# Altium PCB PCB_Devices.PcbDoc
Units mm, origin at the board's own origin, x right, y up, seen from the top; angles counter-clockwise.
Board outline 92.7 x 64.28 mm, 2 copper layers (Top Layer, Bottom Layer); 74 components, 82 nets, 258 pads, 41 vias.
Unrouted connection lines stored in the file: 1.
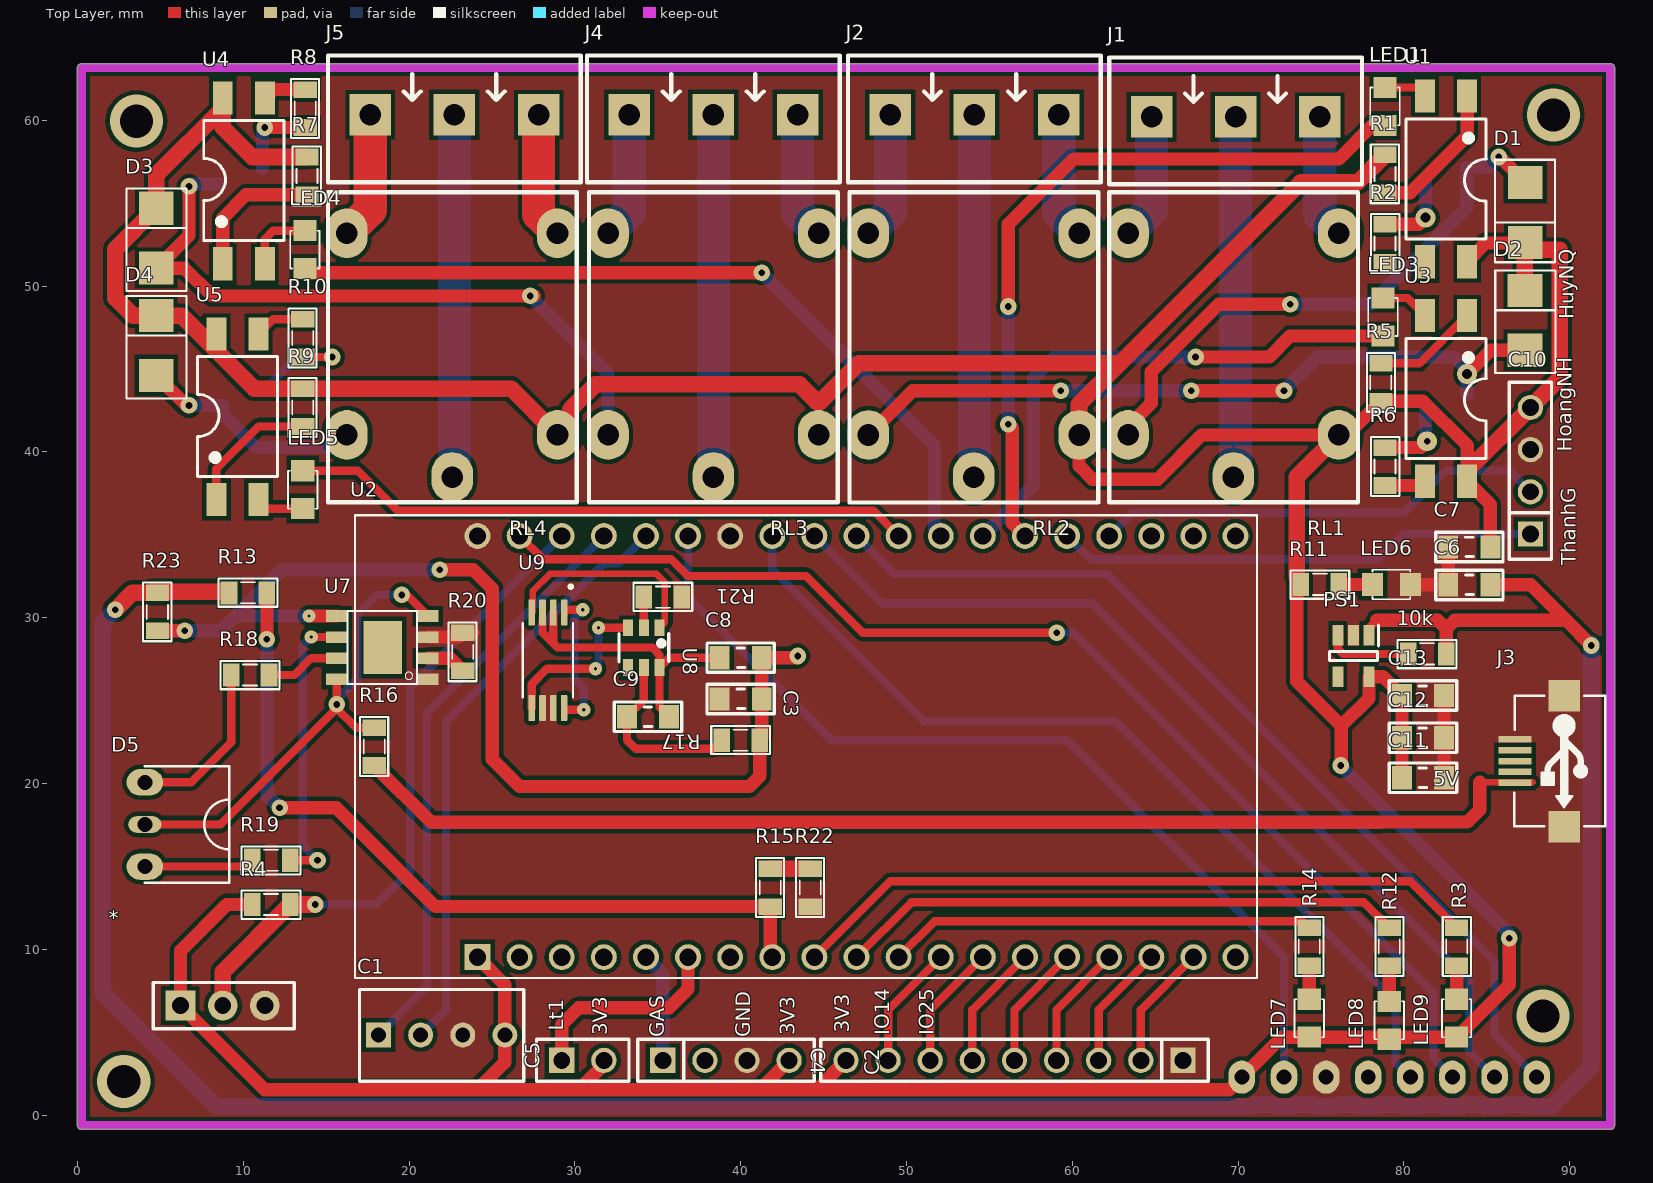
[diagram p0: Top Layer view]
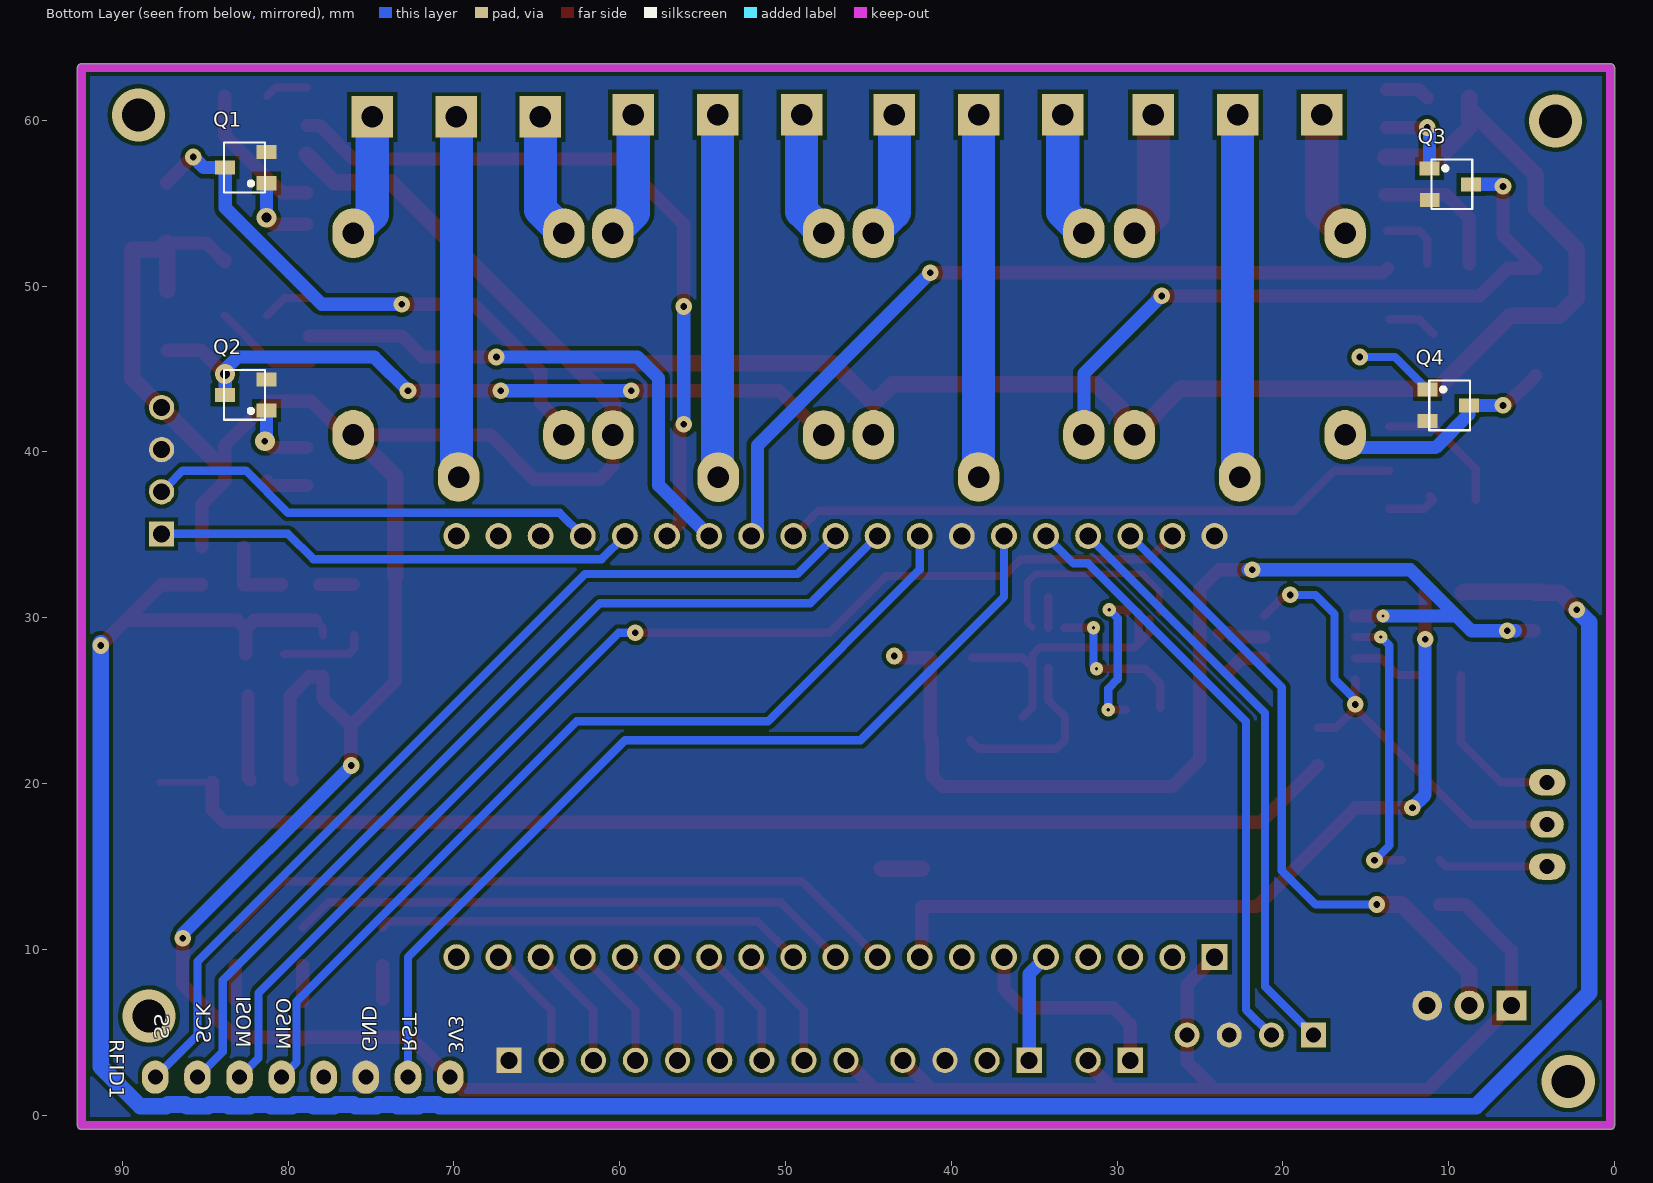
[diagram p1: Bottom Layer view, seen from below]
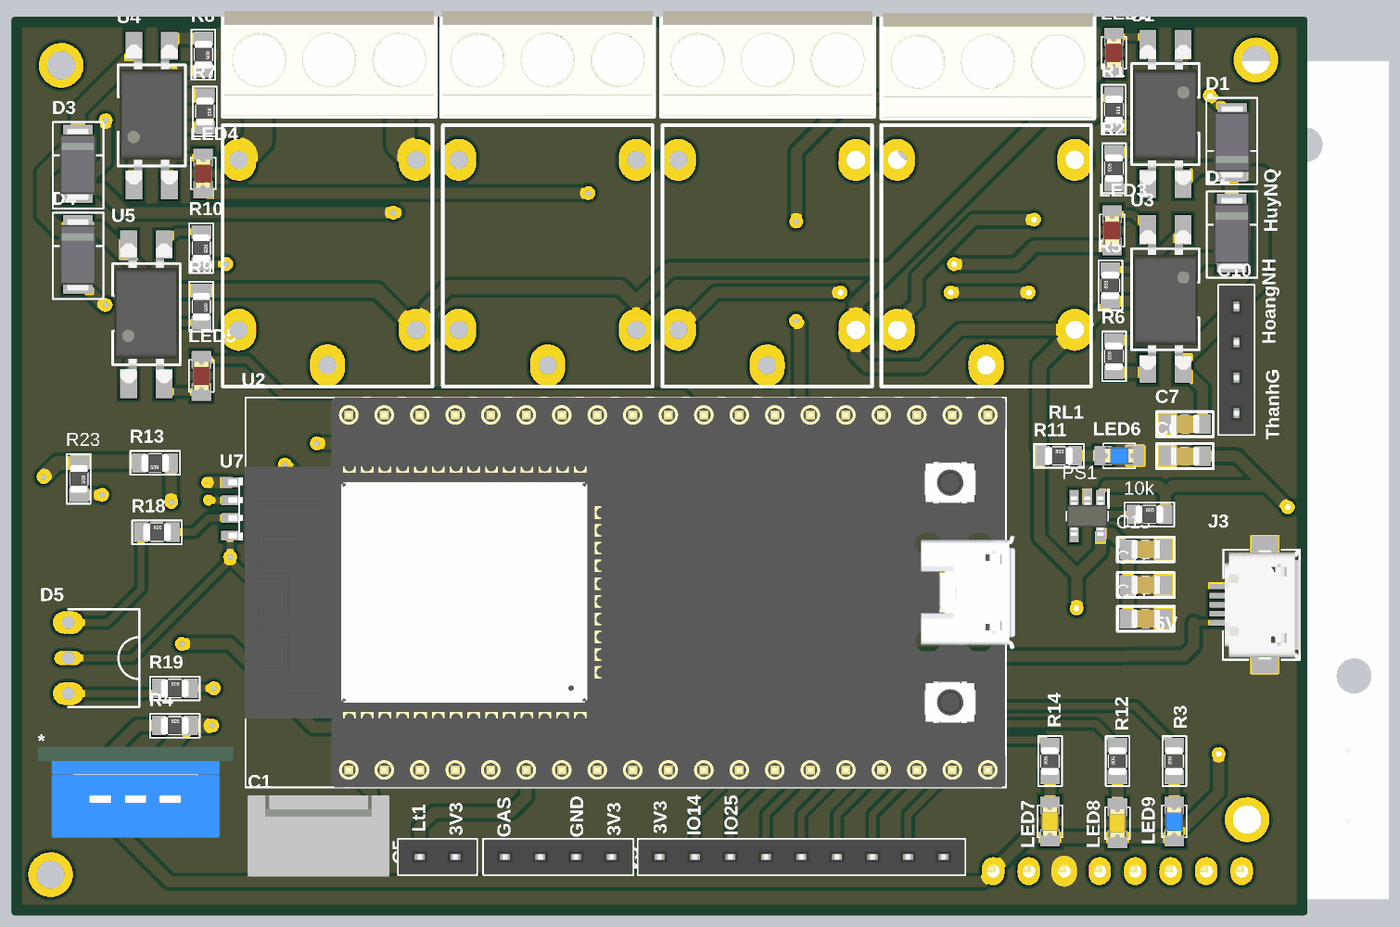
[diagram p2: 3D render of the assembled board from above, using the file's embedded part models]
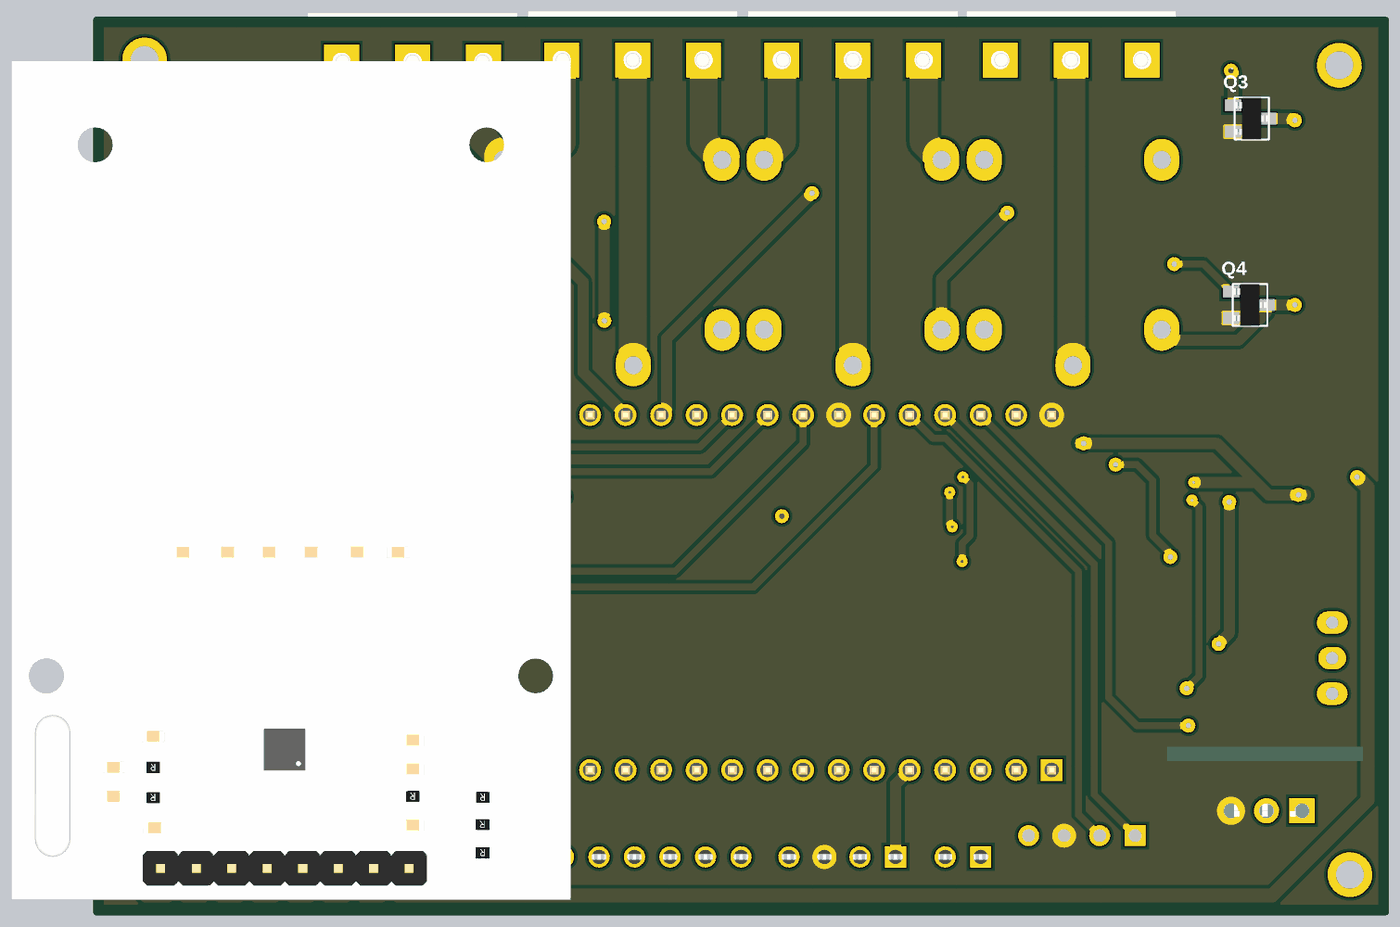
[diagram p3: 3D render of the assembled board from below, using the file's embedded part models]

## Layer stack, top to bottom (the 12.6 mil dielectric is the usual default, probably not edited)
Top Solder: solder mask 0.0102, Solder Resist, Dk 3.5
Top Layer: signal copper 0.0356
Dielectric 1: dielectric 0.32, FR-4, Dk 4.8
Bottom Layer: signal copper 0.0356
Bottom Solder: solder mask 0.0102, Solder Resist, Dk 3.5

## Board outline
0.254,-0.87 cw(c0.254,-0.619) 0.004,-0.619 0.004,63.158 cw(c0.254,63.158) 0.254,63.408 92.456,63.408 cw(c92.456,63.158) 92.706,63.158 92.706,-0.619 cw(c92.456,-0.619) 92.456,-0.87

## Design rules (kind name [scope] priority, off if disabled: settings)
Clearance [All] p1: gap=0.254 ignorepadtopadclearanceinfootprint=FALSE
PolygonConnect [All] p1: connectstyle=Direct reliefconductorwidth=0.254 reliefentries=4 polygonreliefangle="90 Angle" airgapwidth=0.254
RoutingVias [All] p1: holewidth=0.711 width=1.27 viastyle="Through Hole" minholewidth=0.711 minwidth=1.27 maxholewidth=0.711 maxwidth=1.27
SolderMaskExpansion [All] p1: expansion=0.102
Width [All] p1: maxlimit=2 minlimit=0.3 preferedwidth=0.5
30 further rules are at their usual default settings.

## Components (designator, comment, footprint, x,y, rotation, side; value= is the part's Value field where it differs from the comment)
10k "1k" RES-SMD-0805 81.407,27.813 r0 top
* "DHT11_MODULE" DHT11_MODULE 10.033,6.604 r0 top
C1 "Header4" HDR4 18.161,4.826 r0 top
C2 "JP9" JP9-C1T 56.515,3.302 r180 top
C3 "10uF" CAP_0805 40.005,25.127 r0 top value=33p
C4 "MQ5-MOD" JP4-C1T 35.306,3.302 r0 top
C5 "JP2" JP2-C1T 29.21,3.302 r0 top
C6 "1uF" CAP_0805 83.947,32.004 r0 top value=33p
C7 "100nF" CAP_0805 83.947,34.29 r0 top value=33p
C8 "10uF" CAP_0805 40.005,27.613 r0 top value=33p
C9 "100nF" CAP_0805 34.417,24.003 r180 top value=33p
C10 "JP4" JP4-C1T 87.63,35.052 r90 top
C11 "100nF" CAP_0805 81.153,20.32 r180 top value=33p
C12 "100nF" CAP_0805 81.153,22.733 r180 top value=33p
C13 "4.7uf" CAP_0805 81.153,25.273 r180 top value=33p
D1 "M7" DO-214AC(SMA) 87.249,54.991 r90 top
D2 "M7" DO-214AC(SMA) 87.376,47.371 r270 top
D3 "M7" DO-214AC(SMA) 4.826,52.324 r270 top
D4 "M7" DO-214AC(SMA) 4.826,45.847 r270 top
D5 "G/R" "LED_3MM_DUAL RA" 4.064,17.526 r90 top value="B/R LED"
J1 "KF3" KF3-5.08 74.93,60.198 r180 top
J2 "KF3" KF3-5.08 59.182,60.325 r180 top
J3 "0473461001" USB-M1 86.694,21.349 r270 top
J4 "KF3" KF3-5.08 43.434,60.325 r180 top
J5 "KF3" KF3-5.08 27.813,60.325 r180 top
LED1 "LED" LED-0805-Red 78.867,61.976 r270 top value="LED 3 ly Single Colour"
LED3 "LED" LED-0805-Red 78.74,49.276 r270 top value="LED 3 ly Single Colour"
LED4 "LED" LED-0805-Red 13.716,53.34 r270 top value="LED 3 ly Single Colour"
LED5 "LED" LED-0805-Red 13.589,36.576 r90 top value="LED 3 ly Single Colour"
LED6 "LED" LED-0805-Blue 78.105,32.004 r0 top value="LED 3 ly Single Colour"
LED7 "LED" LED-0805-Orange 74.295,4.699 r90 top value="LED 3 ly Single Colour"
LED8 "LED" LED-0805-Orange 79.121,4.572 r90 top value="LED 3 ly Single Colour"
LED9 "LED" LED-0805-Blue 83.185,4.699 r90 top value="LED 3 ly Single Colour"
PS1 "RT9013-33GB" SOT94P279X130-5N 76.962,27.686 r270 top
Q1 "2N222" SOT23D 82.55,57.15 r90 bottom value=C1815
Q2 "2N222" SOT23D 82.55,43.434 r90 bottom value=C1815
Q3 "2N222" SOT23D 9.906,56.134 r270 bottom value=C1815
Q4 "2N222" SOT23D 10.033,42.799 r270 bottom value=C1815
R1 "470" RES-SMD-0805 78.867,56.769 r270 top
R2 "1k" RES-SMD-0805 78.867,52.578 r90 top
R3 "1k" RES-SMD-0805 83.185,10.16 r90 top
R4 "10K" RES-SMD-0805 11.684,12.7 r0 top
R5 "470" RES-SMD-0805 78.613,44.196 r90 top
R6 "1k" RES-SMD-0805 78.867,39.116 r90 top
R7 "470R" RES-SMD-0805 13.843,56.642 r270 top
R8 "1k" RES-SMD-0805 13.741,60.706 r270 top
R9 "470R" RES-SMD-0805 13.589,42.672 r270 top
R10 "1k" RES-SMD-0805 13.589,46.863 r270 top
R11 "470R" RES-SMD-0805 74.93,32.004 r0 top
R12 "1k" RES-SMD-0805 79.121,10.16 r90 top
R13 "10k" RES-SMD-0805 10.287,31.496 r180 top
R14 "1k" RES-SMD-0805 74.295,10.16 r90 top
R15 "1k" RES-SMD-0805 41.783,13.716 r270 top
R16 "0.4R" RES-SMD-0805 17.907,22.225 r270 top
R17 "100R" RES-SMD-0805 40.005,22.606 r180 top
R18 "1k" RES-SMD-0805 10.414,26.543 r0 top
R19 "1k" RES-SMD-0805 11.684,15.367 r0 top
R20 "1.2K" RES-SMD-0805 23.241,27.94 r270 top
R21 "1K" RES-SMD-0805 35.306,31.242 r180 top
R22 "0R" RES-SMD-0805 44.196,13.716 r270 top
R23 "0R" RES-SMD-0805 4.826,30.353 r270 top
RFID1 "RFID" "RFID RC522" 79.121,2.286 r180 bottom
RL1 "Relay 10A/12V" RELAY5PIN-10A 69.723,38.481 r0 top value="Relay SPDT, 10A, 12V"
RL2 "Relay 10A/12V" RELAY5PIN-10A 54.06,38.475 r0 top value="Relay SPDT, 10A, 12V"
RL3 "Relay 10A/12V" RELAY5PIN-10A 38.354,38.481 r0 top value="Relay SPDT, 10A, 12V"
RL4 "Relay 10A/12V" RELAY5PIN-10A 22.606,38.481 r0 top value="Relay SPDT, 10A, 12V"
U1 "OPTO PC817 SMD" OPTO_SMD 83.82,61.468 r270 top value=PC817
U2 "ESP32-DEVKITC-32D" MODULE_ESP32-DEVKITC-32D 43.89,22.225 r90 top
U3 "OPTO PC817 SMD" OPTO_SMD 83.82,48.227 r270 top value=PC817
U4 "OPTO PC817 SMD" OPTO_SMD 8.763,51.341 r90 top value=PC817
U5 "OPTO PC817 SMD" OPTO_SMD 8.382,37.117 r90 top value=PC817
U7 "TP4056" TP4056 18.39,28.194 r180 top
U8 "DW01A" SOT23-6 34.163,28.194 r180 top
U9 "FS8205A" FS8205A 28.321,27.432 r270 top

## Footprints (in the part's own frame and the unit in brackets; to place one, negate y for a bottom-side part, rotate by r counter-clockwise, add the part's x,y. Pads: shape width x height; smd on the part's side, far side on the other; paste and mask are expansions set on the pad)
CAP_0805 [mm]
  rect 1.2x1.4 smd: 1(-1.27,-0.025) 2(1.27,-0.025)
  silkscreen extent -2.03,-0.91 2.03,0.86, body extent -1.01,-0.66 1.01,0.61, height 0.61
DHT11_MODULE [mm]
  rect 1.8x1.8 hole 1.02: 1(-3.81,0)
  round 1.8 hole 1.02: 2(-1.27,0) 3(1.27,0)
  silkscreen extent -5.46,-1.4 3.05,1.4, body extent -8.16,-1.93 5.84,4.57, height 28.5
DO-214AC(SMA) [mm] "DO-214AC Diode Smallest Size"
  rect 2x2.1 smd: 1(1.245,-0.076) 2(-2.367,-0.076)
  silkscreen extent -3.56,-1.86 2.62,1.76, body extent -3.13,-1.38 2.07,1.22, height 2.4
FS8205A [mm]
  rrect25% 1.56x0.4 smd: 1(-2.88,1.031) 2(-2.88,0.381) 3(-2.88,-0.269) 4(-2.88,-0.919) 5(2.88,-0.919) 6(2.88,-0.269) 7(2.88,0.381) 8(2.88,1.031)
  silkscreen extent -4.54,-1.46 2.25,1.57, body extent -3.2,-1.4 3.2,1.53, height 1.2
HDR4 [mm] "Connector; Header; 4 Position"
  rect 1.5x1.5 hole 0.9: 1(0,0)
  round 1.5 hole 0.9: 2(2.54,0) 3(5.08,0) 4(7.62,0)
  silkscreen extent -1.14,-2.79 8.76,2.74, body extent -1.27,-2.92 8.89,2.88, height 11.72
JP2-C1T [mm] "2 row, straight, gold plating"
  rect 1.52x1.52 hole 1.02: 1(0,0)
  round 1.52 hole 1.02: 2(2.54,0)
  silkscreen extent -1.52,-1.27 4.06,1.27, body extent -1.52,-1.25 4.06,1.25, height 8.51
JP4-C1T [mm] "4 row, straight, gold plating"
  rect 1.52x1.52 hole 1.02: 1(0,0)
  round 1.52 hole 1.02: 2(2.54,0) 3(5.08,0) 4(7.62,0)
  silkscreen extent -1.52,-1.27 9.14,1.27, body extent -1.52,-1.25 9.14,1.25, height 8.51
JP9-C1T [mm] "9 row, straight, gold plating"
  rect 1.52x1.52 hole 1.02: 1(-10.16,0)
  round 1.52 hole 1.02: 2(-7.62,0) 3(-5.08,0) 4(-2.54,0) 5(0,0) 6(2.54,0) 7(5.08,0) 8(7.62,0) 9(10.16,0)
  silkscreen extent -11.68,-1.27 11.68,1.27, body extent -11.68,-1.25 11.68,1.25, height 8.51
KF3-5.08 [mm]
  rect 2.5x2.5 hole 1.3: 1(0,0) 2(5.08,0) 3(10.147,0)
  silkscreen extent -2.54,-3.58 12.7,4.06, body extent -2.42,-3.51 12.58,3.99, height 10
LED-0805-Blue [mil]
  rect 50x55 smd: 1(0,0) 2(90,0)
  silkscreen extent 0,-35 90,35, body extent 5,-25 85,25, height 43
LED-0805-Orange [mil]
  rect 50x55 smd: 1(0,0) 2(90,0)
  silkscreen extent 0,-35 90,35, body extent 5,-25 85,25, height 43
LED-0805-Red [mil]
  rect 50x55 smd: 1(0,0) 2(90,0)
  silkscreen extent 0,-35 90,35, body extent 5,-25 85,25, height 43
"LED_3MM_DUAL RA" [mm]
  oval 1.6x2.2 hole 0.9: 1(-2.54,0) 3(2.54,0)
  oval 1x2 / inner oval 1.5x2 / far side oval 1.6x2 hole 0.9: 2(0,0)
  silkscreen extent -3.5,-5.08 3.5,0, body extent -2.84,-2.02 2.84,2.02, height 6.4
MODULE_ESP32-DEVKITC-32D [mm]
  rect 1.56x1.56 hole 1.04: 1(-12.7,19.76)
  round 1.56 hole 1.04: 2(-12.7,17.22) 3(-12.7,14.68) 4(-12.7,12.14) 5(-12.7,9.6) 6(-12.7,7.06) 7(-12.7,4.52) 8(-12.7,1.98) 9(-12.7,-0.56) 10(-12.7,-3.1) 11(-12.7,-5.64) 12(-12.7,-8.18) 13(-12.7,-10.72) 14(-12.7,-13.26) 15(-12.7,-15.8) 16(-12.7,-18.34) 17(-12.7,-20.88) 18(-12.7,-23.42) 19(-12.7,-25.96) 20(12.7,19.76) 21(12.7,17.22) 22(12.7,14.68) 23(12.7,12.14) 24(12.7,9.6) 25(12.7,7.06) 26(12.7,4.52) 27(12.7,1.98) 28(12.7,-0.56) 29(12.7,-3.1) 30(12.7,-5.64) 31(12.7,-8.18) 32(12.7,-10.72) 33(12.7,-13.26) 34(12.7,-15.8) 35(12.7,-18.34) 36(12.7,-20.88) 37(12.7,-23.42) 38(12.7,-25.96)
  silkscreen extent -13.95,-27.25 13.95,27.15, body extent -13.97,-27.9 13.97,27.2, height 8.25
OPTO_SMD [mm]
  rect 2x1.2 smd: 1(0,0) 2(0,-2.54) 3(10,-2.54) 4(10,0)
  silkscreen extent 1.4,-3.68 8.64,1.15, body extent 0.08,-3.56 10.08,1.02, height 3.95
RELAY5PIN-10A [mm]
  oval 2.5x3 hole 1.3: 1(0,0) 2(-6.35,14.7) 3(6.35,14.7) 4(-6.35,2.54) 5(6.35,2.54)
  silkscreen extent -7.49,-1.52 7.51,17.18, body extent -7.49,-1.52 7.49,17.14, height 16
RES-SMD-0805 [mil]
  rect 39.37x55 smd: 1(-45,0) 2(45,0)
  silkscreen extent -70,-34 70,33, body extent -39,-25 39,25, height 31
"RFID RC522" [mm] "RFID RC522"
  oval 1.6x2 hole 0.9: 1(-8.89,0) 2(-6.35,0) 3(-3.81,0) 4(-1.27,0) 5(1.27,0) 6(3.81,0) 7(6.35,0) 8(8.89,0)
  body extent -19.43,-2.03 20.57,57.97, height 15.74
SOT23-6 [mm]
  rect 0.6x1 smd: 1(-0.95,-1.2) 2(0,-1.2) 3(0.95,-1.2) 4(0.95,1.2) 5(0,1.2) 6(-0.95,1.2)
  silkscreen extent -1.5,-0.85 1.5,0.85, body extent -1.46,-1.17 1.46,1.17, height 1
SOT23D [mm] "SOT 23C - 1-3-2 - BCE"
  rect 0.85x1.2 smd: 1(-0.95,-1.25) 2(0.94,-1.245) 3(0,1.25)
  silkscreen extent -1.5,-1.14 1.5,1.32, body extent -1.5,-1.17 1.5,1.33, height 1.06
SOT94P279X130-5N [mm]
  rect 1.25x0.65 smd: 1(-1.25,0.94) 2(-1.25,0) 3(-1.25,-0.94) 4(1.25,-0.94) 5(1.25,0.94)
  silkscreen extent -1.88,-1.45 0.28,1.51, body extent -1.4,-1.45 1.4,1.45, height 1.3
TP4056 [mm]
  rect 1.3x0.7 smd: 1(-2.75,1.905) 2(-2.75,0.635) 3(-2.75,-0.635) 4(-2.75,-1.905) 5(2.75,-1.905) 6(2.75,-0.635) 7(2.75,0.635) 8(2.75,1.905)
  rect 2.3x3.2 smd: GND(-0.025,0)
  silkscreen extent -2.1,-2.2 2.1,2.2, body extent -3.13,-2.45 2.87,2.45, height 1.75
USB-M1 [mm]
  rect 0.4x2 smd: 1(1.3,0) 2(0.65,0) 3(0,0) 4(-0.65,0) 5(-1.321,0)
  rect 1.9x1.9 smd: 5(-3.95,2.968) 5(3.95,2.968)
  silkscreen extent -3.94,-0.03 3.94,5.46, body extent -3.98,0.11 4,5.54, height 2.71

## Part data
10k R1 R2 R3 R4 R5 R6 R7 R8 R9 R10 R11 R12 R13 R14 R15 R16 R17 R18 R19 R20 R21 R22 R23: library part "Resistor - SMD", "Resistor", Manufacturer="Generic Components"
C1: "Header IDC, 4 x 1 Pin Vertical 2.54mm Pitch (Non-Boxed, Male)", Manufacturer="W¨¹rth Elektronik eiSos GmbH", partNo=613002143121
C2: "WR-PHD 2.54 mm Angled Socket Header", Manufacturer="W¨¹rth Elektronik eiSos GmbH", partNo=613009143121
C3 C6 C7 C8 C9 C11 C12 C13: library part CapSMD, "Capacitor"
C4: Manufacturer="W¨¹rth Elektronik eiSos GmbH", partNo=613004143121
C5: "WR-PHD 2.54 mm Angled Socket Header", Manufacturer="W¨¹rth Elektronik eiSos GmbH", partNo=613002143121
C10: "WR-PHD 2.54 mm Angled Socket Header", Manufacturer="W¨¹rth Elektronik eiSos GmbH", partNo=613004143121
D1 D2 D3 D4: library part "Diode M7 ( 4007 )", "Dán"
D5: library part LED_3MM_RA, "LED BLUE/RED DIFFUSED T-1 T/H 3MM", MFR=SunLED, MPN=XLMDKCBD34M
J1 J2 J4 J5: Manufacturer="Würth Elektronik eiSos GmbH", partNo=691103110003
J3: "Connector", Manufacturer_Name=Molex, Mouser Part Number=N/A
LED1 LED3 LED4 LED5 LED6 LED7 LED8 LED9: "LED Single colour Green and Red"
PS1: "Power Supply", Manufacturer_Name=RICHTEK
Q1 Q2 Q3 Q4: "NPN 600mW, ECB"
RFID1: library part "RFID RC522"
RL1 RL2 RL3 RL4: library part "Relay 5", "Relay SPDT,10A - 12VDC 5 Pin"
U1 U3 U4 U5: "Single Opto"
U2: "EVAL BOARD FOR ESP-WROOM-32", Package=None
U7: "Complete single cell Li-Ion battery with a constant current / constant voltage linear charger"
U8: "One Cell Lithium-ion/Polymer Battery Protection IC"

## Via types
v1: diameter 1, hole 0.4, Top Layer to Bottom Layer, 28 vias
v2: diameter 0.8, hole 0.2, Top Layer to Bottom Layer, 6 vias
v3: diameter 3.2, hole 2, Top Layer to Bottom Layer, 4 vias
v4: diameter 1.2, hole 0.6, Top Layer to Bottom Layer, 2 vias
v5: diameter 1.2, hole 0.4, Top Layer to Bottom Layer, 1 vias

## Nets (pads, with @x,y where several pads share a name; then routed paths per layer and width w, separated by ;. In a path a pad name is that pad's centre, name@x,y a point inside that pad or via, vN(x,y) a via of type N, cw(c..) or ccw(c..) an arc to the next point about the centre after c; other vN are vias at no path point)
+3V3: *.1 C1.4 C2.9 C4.4 C5.2 C7.2 C10.4 C11.2 C12.2 C13.2 D1.2 D2.2 D3.2 D4.2 LED7.1 LED8.1 LED9.1 PS1.5 R1.1 R4.1 R5.1 R7.1 R9.1 R11.1 RFID1.8 RL1.5 RL2.5 RL3.5 RL4.5 U1.4 U2.1 U3.4 U4.4 U5.4 | length 337
  Top Layer w0.8: R4.1 9.017,12.7 6.223,9.906 *.1 11.303,1.524 24.13,1.524 ; U2.1 25.781,7.874 C1.4 25.781,3.175 24.13,1.524 ; C5.2 31.75,3.048 30.226,1.524 ; C4.4 41.148,1.524 ; C2.9 44.577,1.524 ; RL2.5 60.41,39.158 61.214,38.354 65.151,38.354 67.818,41.021 RL1.5 76.581,41.021 R5.1 81.153,43.053 83.82,40.386 83.82,38.862 U3.4 85.217,36.83 C7.2 ; R11.1@73.533,32.512 73.533,26.162 76.225,23.47 ; v1(76.2,21.082) 76.225,21.107 76.225,23.47 ; C11.2@79.756,20.218 C11.2 C12.2 C13.2 78.745,26.436 PS1.5 77.902,25.146 76.225,23.47 ; U1.4@83.82,51.593 U1.4 84.95,52.598 D1.2@87.3,52.598 ; v1(86.36,10.668) 86.36,7.874 LED9.1 79.248,4.699 LED8.1 78.994,4.699 LED7.1 72.644,4.699 RFID1.8 69.469,1.524 44.577,1.524 ; 24.13,1.524 30.226,1.524 ; 30.226,1.524 41.148,1.524 ; 41.148,1.524 44.577,1.524
  Top Layer w1: U4.4 U4.4@8.763,60.706 ; R7.1 10.541,57.785 8.763,59.563 U4.4@8.763,60.706 ; RL2.5 60.41,42.884 62.865,45.339 ; R11.1@73.533,32.512 73.533,38.481 RL1.5 ; R1.1 77.216,56.261 73.787,56.261 62.865,45.339 ; U3.4@83.82,38.862 C10.4 89.408,44.45 89.408,52.197 87.752,52.197 D1.2 87.3,52.598 D2.2 ; U4.4@8.763,60.706 4.75,56.693 D3.2 2.286,52.228 2.286,49.276 3.348,48.214 D4.2 6.269,48.214 10.668,43.815 R9.1 26.162,43.815 RL4.5 29.718,41.783 29.718,42.545 31.242,44.069 43.561,44.069 44.704,42.926 47.117,45.339 62.865,45.339
  Bottom Layer w0.8: v1(76.2,21.082) 86.36,10.922 v1(86.36,10.668)
+5V: J3.1 R16.2 | length 73.2
  Top Layer w0.4: 84.582,20.066 87.757,20.066
  Top Layer w0.8: R16.2 21.336,17.653 78.613,17.653 79.991,17.678 83.845,17.678 84.582,18.415 84.582,20.066
GAS_OUT: C4.1 U2.5 | length 6.6
  Bottom Layer w0.8: U2.5 35.306,8.509 C4.1
GND: *.3 C1.3 C2.1 C3.1 C4.3 C6.1 C7.1 C10.3 C11.1 C12.1 C13.1 J3.5 LED6.2 PS1.2 Q1.2 Q2.2 Q3.2 Q4.2 R20.1 R21.1 R22.2 RFID1.6 U2.20 U2.26 U7.1 U7.3 U9.6 U9.7 | length 12.3
  Top Layer w0.5: R20.1@23.749,28.829 24.003,29.083
  Top Layer w0.8: U7.3 22.987,28.829 R20.1 ; LED6.2 80.416,31.979 C6.1 C7.1 ; C11.1@82.296,20.218 C11.1 C12.1 C13.1
Light_2: C5.1 U2.6 | length 12.6
  Top Layer w0.8: C5.1 29.21,5.461 30.226,6.477 35.687,6.477 36.83,7.62 U2.6
LIPO: C3.2 C8.2 R17.1 R23.2 U7.5 | length 65.8
  Top Layer w0.8: R23.2 v1(6.477,29.21) ; v2(13.97,30.099) U7.5 ; v1(21.844,32.893) 23.876,32.893 25.019,31.75 25.019,21.463 26.67,19.812 40.513,19.812 41.148,20.447 R17.1 41.275,22.733 C3.2 C8.2 43.336,27.588 v1(43.434,27.686)
  Bottom Layer w0.8: 5.969,29.21 v1(6.477,29.21) 8.636,29.21 9.525,30.099 ; v2(13.97,30.099) 9.525,30.099 ; v1@22.098,32.893 v1(21.844,32.893) 12.319,32.893 9.525,30.099
Net10k_1: 10k.1 PS1.3 | length 5.2
  Top Layer w0.5: PS1.3 76.022,28.118 76.333,27.807 80.258,27.807 10k.1
NetC1_1: C1.1 U2.23 | length 35.7
  Bottom Layer w0.5: C1.1 21.082,7.747 21.082,24.257 U2.23
NetC2_2: C2.2 U2.18 | length 7.5
  Top Layer w0.5: C2.2 64.135,6.35 U2.18
NetC2_3: C2.3 U2.17 | length 7.5
  Top Layer w0.5: C2.3 61.595,6.35 U2.17
NetC2_4: C2.4 U2.16 | length 7.5
  Top Layer w0.5: C2.4 59.055,6.35 U2.16
NetC2_5: C2.5 U2.15 | length 7.5
  Top Layer w0.5: C2.5 56.515,6.35 U2.15
NetC2_6: C2.6 U2.14 | length 7.5
  Top Layer w0.5: C2.6 53.975,6.35 U2.14
NetC2_7: C2.7 U2.13 | length 7.5
  Top Layer w0.5: C2.7 51.435,6.35 U2.13
NetC2_8: C2.8 U2.12 | length 7.5
  Top Layer w0.5: C2.8 48.895,6.35 U2.12
NetC8_1: C8.1 C9.1 U8.6 U9.2 U9.3 | length 18.1
  Top Layer w0.5: U9.3@28.052,29.902 28.052,29.098 28.702,28.448 ; U9.2 28.702,28.448 ; C9.1 35.113,24.602 U8.6 ; C8.1 35.707,27.588 U8.6 ; 28.702,28.448 28.956,28.194 34.671,28.194 35.113,27.752 U8.6
NetC9_2: C9.2 R17.2 U8.5 | length 10.9
  Top Layer w0.5: U8.5 34.163,25.044 C9.2 33.147,22.606 33.655,22.098 38.354,22.098 R17.2
NetC10_1: C10.1 U2.34 | length 29.5
  Bottom Layer w0.5: U2.34 61.087,33.528 78.486,33.528 80.01,35.052 C10.1 C10.1@88.011,35.052
NetC10_2: C10.2 U2.35 | length 28
  Bottom Layer w0.5: U2.35 63.627,36.322 80.01,36.322 82.55,38.862 86.36,38.862 87.376,37.846 C10.2@88.138,37.846
NetD1_1: D1.1 Q1.3 RL1.4 | length 34.4
  Top Layer w0.8: RL1.4 63.373,41.529 64.77,42.926 64.77,44.831 68.834,48.895 v1(73.152,48.895) ; v1(85.725,57.785) 85.776,57.785 D1.1
  Bottom Layer w0.8: v1(73.152,48.895) 77.978,48.895 83.8,54.717 Q1.3 85.09,57.15 v1(85.725,57.785)
NetD2_1: D2.1 Q2.3 RL2.4 | length 44
  Top Layer w0.8: RL2.4 50.382,43.688 v1(59.309,43.688) ; v1(67.183,43.688) v1(72.771,43.688) ; v4(83.8,44.684) 85.242,46.126 D2.1
  Bottom Layer w0.8: v1(59.309,43.688) v1(67.183,43.688) ; v1(72.771,43.688) 74.803,45.72 83.058,45.72 83.8,44.978 v4(83.8,44.684) Q2.3
NetD3_1: D3.1 Q3.3 RL3.4 | length 41.6
  Top Layer w0.8: v1(6.731,56.007) 6.731,53.061 D3.1 6.452,51.079 8.128,49.403 v1(27.305,49.403) v1@27.559,49.403
  Bottom Layer w0.8: v1(6.731,56.007) 6.858,56.134 Q3.3 ; v1(27.305,49.403) 32.004,44.704 RL3.4
NetD4_1: D4.1 Q4.3 RL4.4 | length 13.9
  Top Layer w0.8: D4.1 6.553,42.799 v1(6.731,42.799)
  Bottom Layer w0.8: v1(6.731,42.799) Q4.3 8.783,42.271 10.795,40.259 15.494,40.259 RL4.4
NetD5_1: D5.1 R19.1 | length 6.6
  Top Layer w0.5: D5.1 10.16,14.986 R19.1
NetD5_2: D5.2 R16.1 U7.4 U7.8 | length 30.6
  Top Layer w0.5: D5.2@3.683,17.526 D5.2 8.636,17.526 v1@15.64,24.53 ; U7.8 v1(15.64,24.765) v1@15.64,24.53 ; R16.1 16.801,23.368 v1@15.64,24.53 ; v1(19.558,31.369) 19.87,31.369 U7.4
  Bottom Layer w0.5: v1(15.64,24.765) 15.64,25.038 16.891,26.289 16.891,30.226 18.034,31.369 v1(19.558,31.369)
NetD5_3: D5.3 R18.1 | length 10.3
  Top Layer w0.5: D5.3 6.858,20.066 9.271,22.479 R18.1
NetJ1_1: J1.1 RL1.3 | length 7.5
  Bottom Layer w2: J1.1 74.93,54.324 RL1.3
NetJ1_2: J1.2 RL1.1 | length 21.8
  Bottom Layer w2: RL1.1 69.85,38.608 J1.2
NetJ1_3: J1.3 RL1.2 | length 7.6
  Bottom Layer w2: RL1.2 64.783,54.591 J1.3
NetJ2_1: J2.1 RL2.3 | length 7.7
  Bottom Layer w2: J2.1 59.182,54.403 RL2.3
NetJ2_2: J2.2 RL2.1 | length 22.1
  Bottom Layer w2: RL2.1 54.102,38.518 J2.2 J2.2@54.102,60.579
NetJ2_3: J2.3 RL2.2 | length 7.7
  Bottom Layer w2: RL2.2 49.035,54.5 J2.3
NetJ4_1: J4.1 RL3.3 | length 7.7
  Bottom Layer w2: J4.1 43.434,54.451 RL3.3
NetJ4_2: J4.2 RL3.1 | length 21.8
  Bottom Layer w2: RL3.1 J4.2
NetJ4_3: J4.3 RL3.2 | length 7.7
  Bottom Layer w2: RL3.2 33.287,54.464 J4.3
NetJ5_1: J5.1 RL4.3 | length 7.6
  Top Layer w2: J5.1 27.813,54.324 RL4.3
NetJ5_2: J5.2 RL4.1 | length 21.9
  Bottom Layer w2: RL4.1 22.733,38.608 J5.2
NetJ5_3: J5.3 RL4.2 | length 7.7
  Top Layer w2: RL4.2 17.666,54.591 J5.3
NetLED1_1: LED1.1 U1.2 | length 2.6
  Top Layer w0.5: LED1.1 80.772,61.976 U1.2
NetLED3_1: LED3.1 U3.2 | length 3
  Top Layer w0.5: LED3.1 80.231,49.276 U3.2
NetLED4_1: LED4.1 U4.2 | length 4.1
  Top Layer w0.5: U4.2 11.303,52.832 11.811,53.34 LED4.1
NetLED5_1: LED5.1 U5.2 | length 3.2
  Top Layer w0.5: U5.2@11.143,37.338 U5.2 11.463,36.576 LED5.1
NetLED6_1: LED6.1 R11.2 | length 2
  Top Layer w0.8: R11.2 LED6.1
NetLED7_2: LED7.2 R14.1 | length 2
  Top Layer w0.8: LED7.2 R14.1
NetLED8_2: LED8.2 R12.1 | length 2.2
  Top Layer w0.8: LED8.2 R12.1
NetLED9_2: LED9.2 R3.1 | length 2
  Top Layer w0.8: LED9.2 R3.1
NetQ1_1: Q1.1 R2.2 | length 4.7
  Top Layer w0.8: R2.2 80.899,53.721 v4(81.3,54.122)
  Bottom Layer w0.8: v4@81.28,54.102 v4(81.3,54.122) Q1.1
NetQ2_1: Q2.1 R6.2 | length 4.6
  Top Layer w0.8: R6.2 81.026,40.259 v5(81.407,40.64)
  Bottom Layer w0.8: Q2.1 81.3,40.747 v5(81.407,40.64)
NetQ3_1: Q3.1 R8.2 | length 5
  Top Layer w0.8: v1(11.303,59.563) R8.2
  Bottom Layer w0.8: Q3.1 11.156,59.416 v1(11.303,59.563)
NetQ4_1: Q4.1 R10.2 | length 6.7
  Top Layer w0.5: R10.2 v1(15.367,45.72)
  Bottom Layer w0.5: Q4.1 13.254,45.72 v1(15.367,45.72)
NetR1_2: R1.2 U1.1 | length 8.8
  Top Layer w0.8: R1.2 80.391,55.626 83.82,59.055 U1.1
NetR2_1: R2.1 U1.3
NetR5_2: R5.2 U3.1 | length 6.4
  Top Layer w0.5: R5.2 80.932,45.339 U3.1
NetR6_1: R6.1 U3.3 | length 2.5
  Top Layer w0.8: R6.1 81.026,37.973 U3.3
NetR7_2: R7.2 U4.1 | length 8.4
  Top Layer w0.8: U4.1 8.763,54.102 10.16,55.499 R7.2
NetR8_1: R8.1 U4.3 | length 2.6
  Top Layer w0.8: U4.3 11.811,61.849 R8.1
NetR9_2: R9.2 U5.1 | length 8.1
  Top Layer w0.5: U5.1 8.382,38.989 10.922,41.529 R9.2
NetR10_1: R10.1 U5.3 | length 3
  Top Layer w0.5: U5.3 11.811,48.006 R10.1
NetR15_1: R15.1 R22.1 | length 2.4
  Top Layer w1: R15.1 R22.1
NetR18_2: R18.2 U7.7 | length 4.5
  Top Layer w0.5: R18.2 13.081,26.543 14.097,27.559 U7.7
NetR19_2: R19.2 U7.6 | length 17.2
  Top Layer w0.5: R19.2 v1(14.478,15.367) ; v2(14.097,28.829) U7.6
  Bottom Layer w0.5: v2(14.097,28.829) 13.589,28.321 13.589,16.256 v1(14.478,15.367)
NetR20_2: R20.2 U7.2 | length 2.4
  Top Layer w0.8: U7.2 22.479,27.559 R20.2
NetR21_2: R21.2 U8.2 | length 1.8
  Top Layer w0.5: U8.2 R21.2
NetU8_1: U8.1 U9.4 | length 12.8
  Top Layer w0.4: U9.4 27.452,30.362 27.452,31.596 28.495,32.639 34.925,32.639 35.433,32.131 35.433,29.714 U8.1
NetU8_3: U8.3 U9.5 | length 10.1
  Top Layer w0.5: U9.5 27.402,26.005 28.321,26.924 v2(31.242,26.924) ; v2@31.369,29.337 v2(31.426,29.394) U8.3
  Bottom Layer w0.5: v2(31.242,26.924) 31.426,27.108 v2(31.426,29.394)
NetU9_1: U9.1 U9.8 | length 8.7
  Top Layer w0.5: U9.1@29.402,30.312 29.402,30.362 29.52,30.48 v2(30.48,30.48) ; U9.8@29.463,24.441 v2(30.537,24.441)
  Bottom Layer w0.5: v2(30.48,30.48) 29.972,29.972 29.972,26.289 30.537,25.724 v2(30.537,24.441)
PIN_adc: R13.1 R15.2 U2.8 | length 48.4
  Top Layer w0.8: v1(11.43,28.702) R13.1 ; v1(12.192,18.542) 15.621,18.542 21.59,12.573 R15.2 41.783,9.652 U2.8
  Bottom Layer w0.8: v1(11.43,28.702) 11.43,19.304 v1(12.192,18.542)
PIN_led1: R3.2 U2.9 | length 41.8
  Top Layer w0.5: U2.9 49.022,14.097 80.391,14.097 R3.2
PIN_led2: R12.2 U2.10 | length 34.1
  Top Layer w0.5: U2.10 50.292,12.827 77.597,12.827 R12.2
PIN_led3: R14.2 U2.11 | length 25.8
  Top Layer w0.5: U2.11 51.689,11.684 73.914,11.684 R14.2
PIN_lipo: 10k.2 C6.2 PS1.1 R13.2 R23.1 | length 173
  Top Layer w0.5: PS1.1 77.902,29.388 78.359,29.845
  Top Layer w0.8: 78.359,29.845 82.042,29.845 82.55,29.337 ; 10k.2 82.55,29.337 ; C6.2 87.655,31.979 89.789,29.845 ; v1(91.313,28.321) 89.789,29.845 ; 82.55,29.337 83.058,29.845 89.789,29.845
  Top Layer w1: v1(2.286,30.48) 3.302,31.496 R23.1 ; R23.1@4.418,31.575 9.065,31.575 R13.2
  Bottom Layer w1: v1(2.286,30.48) 1.524,29.718 1.524,7.366 8.358,0.532 70.875,0.532 70.978,0.635 72.024,0.635 72.127,0.532 73.415,0.532 73.518,0.635 74.564,0.635 74.667,0.532 75.955,0.532 76.058,0.635 77.104,0.635 77.207,0.532 78.495,0.532 78.598,0.635 79.644,0.635 79.747,0.532 81.035,0.532 81.138,0.635 82.184,0.635 82.287,0.532 83.575,0.532 83.678,0.635 84.724,0.635 84.827,0.532 86.115,0.532 86.218,0.635 87.264,0.635 87.367,0.532 88.924,0.532 91.313,2.921 v1@91.313,28.448
RFID_MISO: RFID1.4 U2.27 | length 55.3
  Bottom Layer w0.5: U2.27 41.91,32.893 51.054,23.749 62.611,23.749 79.502,6.858 79.502,3.175 RFID1.4
RFID_MOSI: RFID1.3 U2.21 | length 72.1
  Top Layer w0.5: U2.21 28.067,33.528 35.814,33.528 36.83,32.512 43.942,32.512 47.371,29.083 v1(59.055,29.083)
  Bottom Layer w0.5: v1(59.055,29.083) 60.071,29.083 81.788,7.366 81.788,3.429 RFID1.3
RFID_RST: RFID1.7 U2.25 | length 55.9
  Bottom Layer w0.5: U2.25 36.83,31.242 45.466,22.606 59.69,22.606 72.771,9.525 RFID1.7
RFID_SCK: RFID1.2 U2.28 | length 57.1
  Bottom Layer w0.5: U2.28 48.514,30.861 61.214,30.861 83.947,8.128 83.947,3.81 RFID1.2
RFID_SS: RFID1.1 U2.29 | length 57.1
  Bottom Layer w0.5: U2.29 49.276,32.639 62.103,32.639 85.471,9.271 85.471,4.826 RFID1.1
RL1: LED1.2 U2.33 | length 44.4
  Top Layer w0.8: v1(56.134,41.656) 56.388,41.434 56.388,35.687 U2.33 ; v1(56.143,48.768) 56.143,53.73 60.071,57.658 76.073,57.658 78.105,59.69 LED1.2
  Bottom Layer w0.8: v1(56.134,41.656) 56.143,41.665 v1(56.143,48.768)
RL2: LED3.2 U2.32 | length 32.9
  Top Layer w0.8: v1(67.437,45.72) 71.882,45.72 73.152,46.99 LED3.2
  Bottom Layer w0.8: U2.32 57.658,37.973 57.658,44.45 58.928,45.72 v1(67.437,45.72)
RL3: LED4.2 U2.31 | length 48
  Top Layer w0.8: LED4.2 13.97,50.8 v1(41.275,50.8)
  Bottom Layer w0.8: v1(41.275,50.8) 51.689,40.386 51.689,35.306 U2.31
RL4: LED5.2 U2.30 | length 37.6
  Top Layer w0.5: LED5.2 16.891,38.862 19.304,36.449 48.006,36.449 U2.30
RX0: C1.2 U2.24 | length 36.2
  Bottom Layer w0.5: C1.2 22.225,6.35 22.225,23.749 31.75,33.274 32.639,33.274 U2.24
TEMP: *.2 R4.2 U2.22 | length 39.8
  Top Layer w1: *.2 8.763,8.636 R4.2 v1(14.351,12.7)
  Bottom Layer w0.5: v1(14.351,12.7) 18.034,12.7 20.066,14.732 20.066,25.781 U2.22
pads on no net: C4.2 J3.2 J3.3 J3.4 PS1.4 RFID1.5 U2.2 U2.3 U2.4 U2.7 U2.19 U2.36 U2.37 U2.38 U7.GND U8.4
copper on no net:
  other v3: 2.794,2.032 88.392,5.969 3.556,59.944 89.027,60.325

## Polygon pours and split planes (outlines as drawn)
no net on Top Overlay (solid): -64.404,63.452
GND on Top Layer (solid, pour order 10): 0.254,63.158 0.254,-0.619 92.456,-0.619 92.456,63.158
GND on Bottom Layer (solid, pour order 12): 0.254,62.992 0.254,-0.619 92.456,-0.619 92.456,63.158

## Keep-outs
Keep-Out Layer:
  lines w0.5: 0.254,-0.619 0.254,63.158 92.456,63.158 92.456,-0.619 0.254,-0.619

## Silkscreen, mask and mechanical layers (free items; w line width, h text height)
Top Overlay:
  text "HuyNQ" at 90.551,48.006 h1.52 r90
  text "HoangNH" at 90.424,40.005 h1.52 r90
  text "ThanhG" at 90.678,33.147 h1.52 r90
  text "5V" at 81.788,19.558 h1.52
  text "Lt1" at 29.591,5.08 h1.52 r90
  text "3V3" at 46.863,4.953 h1.52 r90
  text "3V3" at 32.258,4.826 h1.52 r90
  text "3V3" at 43.561,4.826 h1.52 r90
  text "IO14" at 49.276,4.826 h1.52 r90
  text "IO25" at 51.943,4.826 h1.52 r90
  text "GAS" at 35.687,4.699 h1.52 r90
  text "GND" at 40.894,4.699 h1.52 r90
Bottom Overlay:
  text "SS" at 88.392,4.572 h1.52 r90
  text "SCK" at 85.852,4.318 h1.52 r90
  text "MOSI" at 83.439,4.064 h1.52 r90
  text "MISO" at 81.026,3.937 h1.52 r90
  text "RST" at 73.406,3.81 h1.52 r90
  text "GND" at 75.819,3.81 h1.52 r90
  text "3V3" at 70.612,3.683 h1.52 r90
